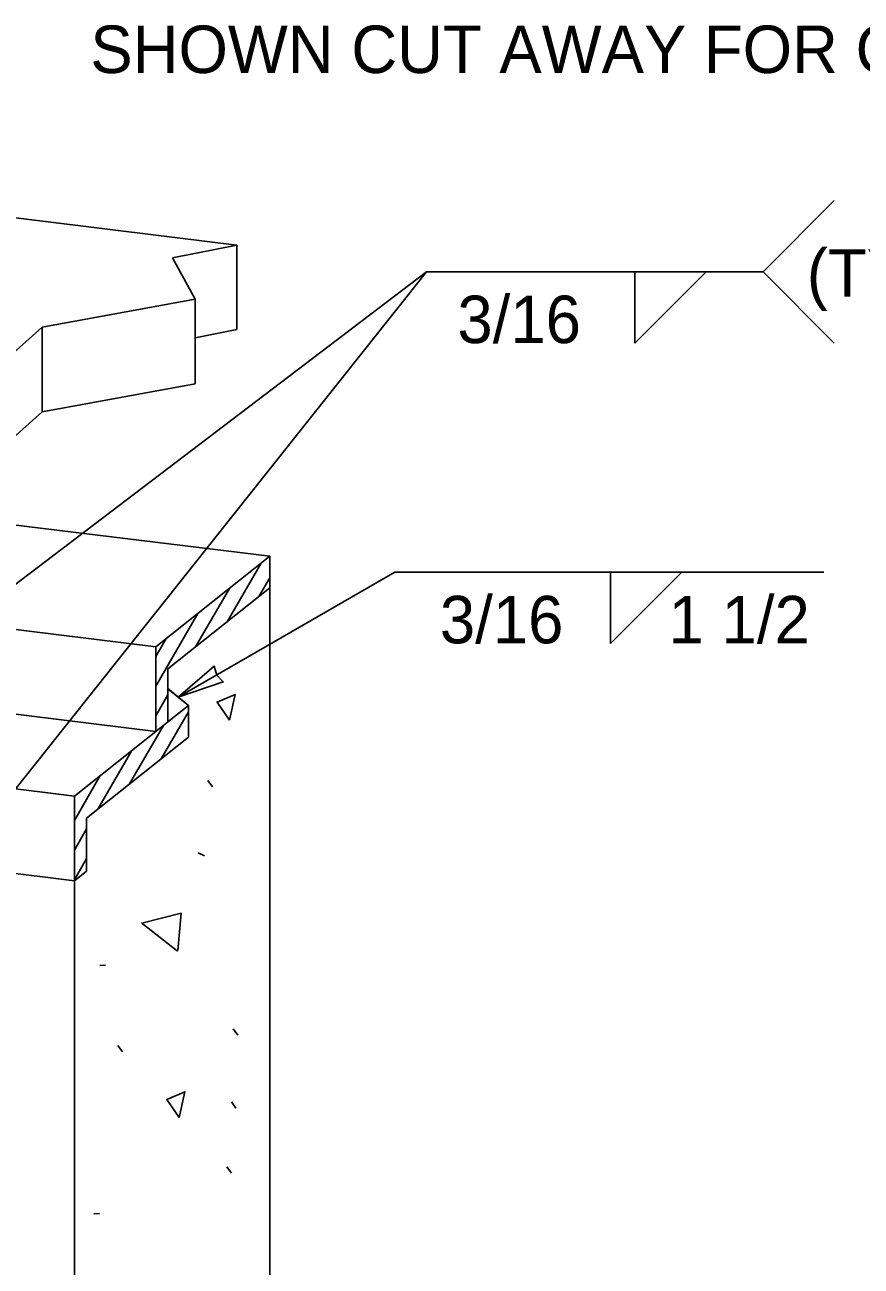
# Model space of a CAD drawing. Extents: x 99862 to 112891, y 95370 to 105076.
# Drawn here: x 102253.7 to 102535.7, y 103267.8 to 103686 of the extents above; entities that cross this region are included whole.
import ezdxf

# ---------------------------------------------------------------- set-up
doc = ezdxf.new("R2010")
doc.units = 0
for name, color, linetype in [('Level 1', 7, 'Continuous'), ('Level 15', 7, 'Continuous'), ('Level 2', 7, 'Continuous'), ('Level 20', 7, 'Continuous'), ('Level 3', 7, 'Continuous'), ('Level 8', 7, 'Continuous')]:
    doc.layers.add(name, color=color, linetype=linetype)

msp = doc.modelspace()

# ---------------------------------------------------------------- linework, layer by layer
at = {"layer": 'Level 1'}
for p, q in [((102336.3, 103496.29), (102336.3, 103243.06)), ((102316.97, 103429.35), (102315.42, 103431.47)), ((102312.14, 103407.06), (102314.35, 103406.1)), ((102270.43, 103190.73), (102270.43, 103397.65)), ((102279.04, 103369.07), (102280.96, 103369.2)), ((102325.55, 103345.61), (102324.01, 103347.73)), ((102286.67, 103340.06), (102285.13, 103342.19)), ((102324.89, 103321.07), (102323.35, 103323.2)), ((102323.41, 103299.17), (102321.86, 103301.29)), ((102276.96, 103285.42), (102278.87, 103285.55))]:
    msp.add_line(p, q, dxfattribs=at)
for points in [[(102322.69, 103451.74), (102318.52, 103457.84), (102324.64, 103460.45), (102322.69, 103451.74)], [(102305.26, 103373.94), (102293.13, 103383.38), (102306.44, 103386.72), (102305.31, 103374.2)], [(102305.76, 103317.89), (102301.59, 103323.99), (102307.72, 103326.61), (102305.76, 103317.89)]]:
    msp.add_lwpolyline(points, dxfattribs=at)
at = {"layer": 'Level 15'}
for p, q in [((102502.57, 103602.76), (102526.57, 103626.76)), ((102389.12, 103602.76), (102148.28, 103419.78)), ((102389.12, 103602.76), (102213.93, 103382.51)), ((102389.12, 103602.76), (102502.57, 103602.76)), ((102459.41, 103602.76), (102459.41, 103578.76)), ((102459.41, 103578.76), (102483.41, 103602.76)), ((102502.57, 103602.76), (102526.57, 103578.76)), ((102305.45, 103459.45), (102378.5, 103501.63)), ((102378.5, 103501.63), (102523.04, 103501.63)), ((102451.21, 103501.63), (102451.21, 103477.63)), ((102451.21, 103477.63), (102475.21, 103501.63))]:
    msp.add_line(p, q, dxfattribs=at)
msp.add_lwpolyline([(102305.45, 103459.45), (102320.61, 103464.64), (102318.44, 103466.95), (102317.52, 103469.99)], close=True, dxfattribs=at)
at = {"layer": 'Level 2'}
for p, q in [((102336.3, 103506.97), (102148.98, 103529.98)), ((102297.88, 103476.45), (101948.05, 103519.42)), ((102336.3, 103506.97), (102297.88, 103476.45)), ((102321.95, 103484.89), (102333.35, 103504.64)), ((102336.3, 103496.29), (102336.3, 103506.97)), ((102332.62, 103493.37), (102336.3, 103499.73)), ((102336.3, 103496.29), (102301.99, 103469.03)), ((102311.29, 103476.42), (102322.69, 103496.16)), ((102297.88, 103447.95), (101948.05, 103490.92)), ((102297.88, 103463.19), (102312.02, 103487.69)), ((102297.88, 103473.19), (102301.35, 103479.21)), ((102297.88, 103476.45), (102297.88, 103447.95)), ((102270.44, 103426.15), (101920.61, 103469.12)), ((102301.99, 103451.22), (102301.99, 103469.03)), ((102297.88, 103453.19), (102301.99, 103460.32)), ((102308.86, 103456.68), (102270.44, 103426.15)), ((102299.74, 103438.74), (102308.86, 103454.54)), ((102308.86, 103445.99), (102308.86, 103456.68)), ((102289.07, 103430.27), (102300.47, 103450.01)), ((102274.56, 103418.73), (102308.86, 103445.99)), ((102278.4, 103421.79), (102289.8, 103441.54)), ((102270.44, 103417.99), (102279.14, 103433.06)), ((102270.44, 103426.15), (102270.44, 103397.65)), ((102274.56, 103400.93), (102274.56, 103418.73)), ((102270.44, 103407.99), (102274.56, 103415.12)), ((102270.43, 103397.65), (102176.19, 103409.23)), ((102270.44, 103397.99), (102274.56, 103405.12)), ((102270.43, 103397.65), (102274.56, 103400.93))]:
    msp.add_line(p, q, dxfattribs=at)
at = {"layer": 'Level 3'}
for p, q in [((102325.2, 103611.81), (101985.31, 103653.56)), ((102303.5, 103607.49), (102325.2, 103611.81)), ((102325.2, 103583.31), (102325.2, 103611.81)), ((102311.18, 103593.55), (102303.5, 103607.49)), ((102259.64, 103584.17), (102311.18, 103593.55)), ((102311.18, 103593.55), (102311.18, 103565.05)), ((102240.88, 103567.39), (102259.64, 103584.17)), ((102259.64, 103584.17), (102259.64, 103555.67)), ((102311.18, 103580.52), (102325.2, 103583.31)), ((102259.64, 103555.67), (102311.18, 103565.05)), ((102240.88, 103538.89), (102259.64, 103555.67))]:
    msp.add_line(p, q, dxfattribs=at)
at = {"layer": 'Level 8'}
msp.add_line((102308.86, 103456.68), (102301.91, 103462.39), dxfattribs=at)
msp.add_lwpolyline([(102301.99, 103462.32), (102301.99, 103460.32), (102301.99, 103451.22), (102308.86, 103456.68), (102301.99, 103462.32)], dxfattribs=at)

# ---------------------------------------------------------------- texts
at = {"layer": 'Level 20'}
for s, p in [('SHOWN CUT AWAY FOR CLARITY', (102275.83, 103669.74)), ('(TYP.)', (102517.33, 103594.39)), ('3/16', (102393.64, 103477.63)), ('1 1/2', (102470.75, 103477.63))]:
    msp.add_text(s, height=16, dxfattribs=at).set_placement(p)
msp.add_text('3/16', height=16, rotation=360, dxfattribs=at).set_placement((102399.55, 103578.76))

doc.saveas('drawing.dxf')
